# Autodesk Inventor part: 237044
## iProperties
Created: 2006-01
Part Number: 237044
Material: FSt
Document SubType Name: Modeling
Designer: I.Baliuc
Manufacturer: Standard
Standards Organization: Custom
Description: Ringfeder
Density: 7.85 g/cm^3
Abmessung: N9
Author: T.Messerschmitt
Revision Number: 237044
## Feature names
1. Basis1
